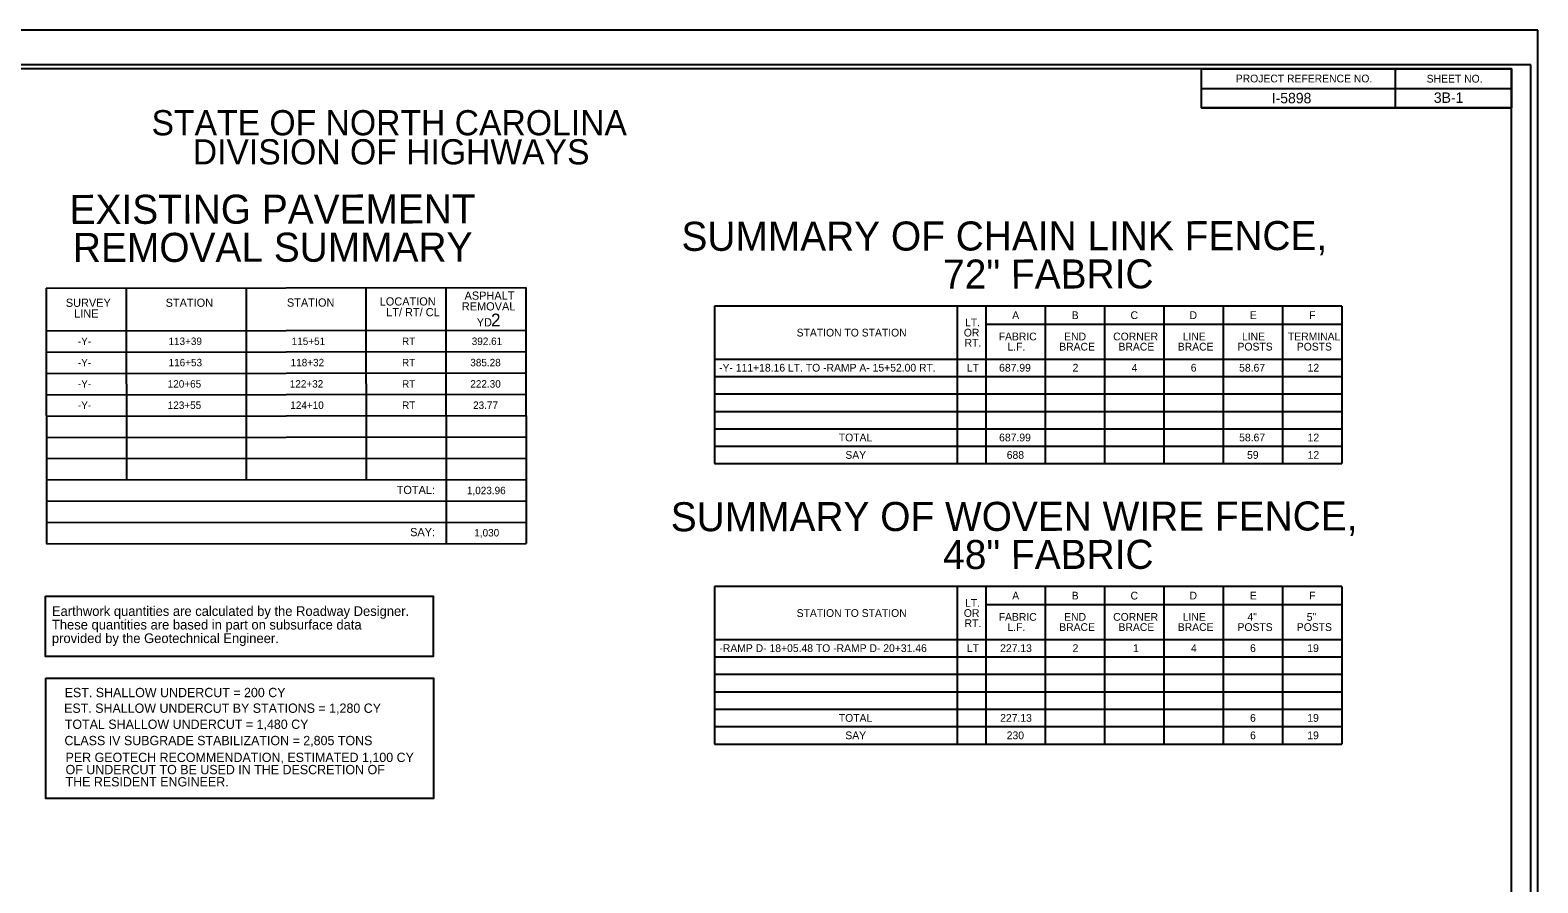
# Model space of a CAD drawing. Extents: x 573692 to 575376, y -53322 to -52222.
# Drawn here: x 574403 to 575376, y -52772 to -52222 of the extents above; entities that cross this region are included whole.
import ezdxf

# ---------------------------------------------------------------- set-up
doc = ezdxf.new("R2010")
doc.units = 0
for name, color, linetype in [('Prop Dimension Text', 7, 'Continuous'), ('Sheet Data Field CELL', 7, 'Continuous'), ('Sheet Plot Border Inside CELL', 7, 'Continuous'), ('Sheet Plot Border Outside CELL', 7, 'Continuous'), ('Sheet Summary Combination CELL', 7, 'Continuous'), ('Sheet Summary Combination Grid CELL', 7, 'Continuous'), ('Sheet Summary Earthwork CELL', 7, 'Continuous')]:
    doc.layers.add(name, color=color, linetype=linetype)

msp = doc.modelspace()

# ---------------------------------------------------------------- linework, layer by layer
at = {"layer": 'Sheet Plot Border Inside CELL'}
msp.add_lwpolyline([(575371.32, -52244.93), (573704.82, -52244.93), (573704.82, -53300.03), (575371.32, -53300.03)], close=True, dxfattribs=at)
at = {"layer": 'Sheet Plot Border Outside CELL'}
msp.add_lwpolyline([(575375.82, -52222.48), (573691.82, -52222.48), (573691.82, -53322.48), (575375.82, -53322.48)], close=True, dxfattribs=at)
at = {"layer": 'Sheet Summary Combination CELL'}
for p, q in [((575283.82, -52247.53), (575283.82, -52272.53)), ((575158.77, -52260.03), (575358.82, -52260.03)), ((575158.77, -52272.53), (575358.82, -52272.53)), ((574568.98, -52388.77), (574568.98, -52388.77)), ((574575.86, -52388.87), (574575.86, -52388.87)), ((574585.81, -52388.64), (574585.81, -52388.64)), ((574591.97, -52388.75), (574591.97, -52388.75))]:
    msp.add_line(p, q, dxfattribs=at)
for points in [[(575358.82, -52247.48), (573858.82, -52247.48), (573858.82, -53297.48), (575358.82, -53297.48)], [(575158.77, -52247.48), (575358.82, -52247.48), (575358.82, -52272.53), (575158.77, -52272.53)]]:
    msp.add_lwpolyline(points, close=True, dxfattribs=at)
at = {"layer": 'Sheet Summary Combination Grid CELL'}
for p, q in [((574413.61, -52388.88), (574723.09, -52388.56)), ((574413.61, -52388.88), (574413.78, -52553.88)), ((574465.2, -52388.82), (574465.33, -52512.57)), ((574542.58, -52388.74), (574542.71, -52512.49)), ((574619.91, -52388.66), (574620.04, -52512.41)), ((574671.5, -52388.61), (574671.67, -52553.61)), ((574723.09, -52388.56), (574723.26, -52553.56)), ((574723.09, -52388.56), (574723.26, -52553.56)), ((574844.82, -52400.56), (574844.82, -52502.1)), ((575249.3, -52400.56), (574844.82, -52400.56)), ((575001.3, -52400.56), (575001.3, -52502.1)), ((575019.8, -52400.56), (575019.8, -52502.1)), ((575058.05, -52400.56), (575058.05, -52502.1)), ((575096.3, -52400.56), (575096.3, -52502.1)), ((575134.55, -52400.56), (575134.55, -52502.1)), ((575172.8, -52400.56), (575172.8, -52502.1)), ((575211.05, -52400.56), (575211.05, -52502.1)), ((575249.3, -52400.56), (575249.3, -52502.1)), ((574413.64, -52416.38), (574723.12, -52416.06)), ((575019.8, -52412.1), (575249.3, -52412.1)), ((574413.65, -52430.13), (574723.14, -52429.81)), ((574844.82, -52434.6), (575249.3, -52434.6)), ((574413.67, -52443.88), (574723.15, -52443.56)), ((574844.82, -52445.85), (575249.3, -52445.85)), ((574413.68, -52457.63), (574723.16, -52457.31)), ((574844.82, -52457.1), (575249.3, -52457.1)), ((574844.82, -52468.35), (575249.3, -52468.35)), ((574413.69, -52471.38), (574723.18, -52471.06)), ((574413.71, -52485.13), (574723.19, -52484.81)), ((574844.82, -52479.6), (575249.3, -52479.6)), ((574844.82, -52490.85), (575249.3, -52490.85)), ((574413.72, -52498.88), (574723.21, -52498.56)), ((574844.82, -52502.1), (575249.3, -52502.1)), ((574413.74, -52512.63), (574723.22, -52512.31)), ((574413.75, -52526.38), (574723.24, -52526.06)), ((574413.77, -52540.13), (574723.25, -52539.81)), ((574413.78, -52553.88), (574723.26, -52553.56)), ((574844.82, -52581.44), (574844.82, -52682.98)), ((575249.3, -52581.44), (574844.82, -52581.44)), ((575001.3, -52581.44), (575001.3, -52682.98)), ((575019.8, -52581.44), (575019.8, -52682.98)), ((575058.05, -52581.44), (575058.05, -52682.98)), ((575096.3, -52581.44), (575096.3, -52682.98)), ((575134.55, -52581.44), (575134.55, -52682.98)), ((575172.8, -52581.44), (575172.8, -52682.98)), ((575211.05, -52581.44), (575211.05, -52682.98)), ((575249.3, -52581.44), (575249.3, -52682.98)), ((575019.8, -52592.98), (575249.3, -52592.98)), ((574844.82, -52615.48), (575249.3, -52615.48)), ((574844.82, -52626.73), (575249.3, -52626.73)), ((574844.82, -52637.98), (575249.3, -52637.98)), ((574844.82, -52649.23), (575249.3, -52649.23)), ((574844.82, -52660.48), (575249.3, -52660.48)), ((574844.82, -52671.73), (575249.3, -52671.73)), ((574844.82, -52682.98), (575249.3, -52682.98))]:
    msp.add_line(p, q, dxfattribs=at)
at = {"layer": 'Sheet Summary Earthwork CELL'}
for points in [[(574413.11, -52587.5), (574663.17, -52587.5), (574663.17, -52626.53), (574413.11, -52626.53)], [(574413.32, -52640.49), (574663.37, -52640.49), (574663.37, -52718.03), (574413.32, -52718.03)]]:
    msp.add_lwpolyline(points, close=True, dxfattribs=at)

# ---------------------------------------------------------------- texts
at = {"layer": 'Prop Dimension Text'}
for s, height, p in [('LT.', 5, (575006.35, -52413.52)), ('A', 5, (575036.76, -52408.83)), ('B', 5, (575075.14, -52408.83)), ('C', 5, (575113.09, -52408.83)), ('D', 5, (575151.15, -52408.83)), ('E', 5, (575190.08, -52408.83)), ('F', 5, (575228.33, -52408.83)), ('STATION TO STATION', 5.0001, (574897.72, -52420.08)), ('OR', 5, (575005.57, -52420.08)), ('FABRIC', 5, (575028.05, -52422.57)), ('END', 5, (575070.28, -52422.57)), ('CORNER', 5, (575101.89, -52422.57)), ('LINE', 5, (575146.73, -52422.57)), ('LINE', 5, (575184.98, -52422.57)), ('TERMINAL', 5, (575214.61, -52422.57)), ('RT.', 5, (575006.06, -52426.63)), ('L.F.', 5, (575033.69, -52429.12)), ('BRACE', 5, (575067.09, -52429.12)), ('BRACE', 5, (575105.34, -52429.12)), ('BRACE', 5, (575143.59, -52429.12)), ('POSTS', 5, (575182.1, -52429.12)), ('POSTS', 5, (575220.35, -52429.12)), ('-Y- 111+18.16 LT. TO -RAMP A- 15+52.00 RT.', 5.0001, (574847.69, -52442.72)), ('LT', 5, (575007.58, -52442.72)), ('687.99', 5, (575028.33, -52442.72)), ('2', 5, (575075.71, -52442.72)), ('4', 5, (575113.82, -52442.72)), ('6', 5, (575151.95, -52442.72)), ('58.67', 5, (575183.15, -52442.72)), ('12', 5, (575227.33, -52442.72)), ('TOTAL', 5, (574924.93, -52487.72)), ('687.99', 5, (575028.33, -52487.72)), ('58.67', 5, (575183.15, -52487.72)), ('12', 5, (575227.33, -52487.72)), ('SAY', 5, (574929.13, -52498.97)), ('688', 5, (575033.23, -52498.97)), ('59', 5, (575188.25, -52498.97)), ('12', 5, (575227.33, -52498.97)), ('A', 5, (575036.76, -52589.71)), ('B', 5, (575075.14, -52589.71)), ('C', 5, (575113.09, -52589.71)), ('D', 5, (575151.15, -52589.71)), ('E', 5, (575190.08, -52589.71)), ('F', 5, (575228.33, -52589.71)), ('LT.', 5, (575006.35, -52594.4)), ('STATION TO STATION', 5.0001, (574897.72, -52600.96)), ('OR', 5, (575005.57, -52600.96)), ('RT.', 5, (575006.06, -52607.51)), ('FABRIC', 5, (575028.05, -52603.45)), ('END', 5, (575070.28, -52603.45)), ('CORNER', 5, (575101.89, -52603.45)), ('LINE', 5, (575146.73, -52603.45)), ('4"', 5, (575188.5, -52603.45)), ('5"', 5, (575226.75, -52603.45)), ('L.F.', 5, (575033.69, -52610.01)), ('BRACE', 5, (575067.09, -52610.01)), ('BRACE', 5, (575105.34, -52610.01)), ('BRACE', 5, (575143.59, -52610.01)), ('POSTS', 5, (575182.1, -52610.01)), ('POSTS', 5, (575220.35, -52610.01)), ('-RAMP D- 18+05.48 TO -RAMP D- 20+31.46', 5.0001, (574847.89, -52623.6)), ('LT', 5, (575007.58, -52623.6)), ('227.13', 5, (575028.99, -52623.6)), ('2', 5, (575075.71, -52623.6)), ('1', 5, (575114.67, -52623.6)), ('4', 5, (575152.07, -52623.6)), ('6', 5, (575190.2, -52623.6)), ('19', 5, (575227.1, -52623.6)), ('TOTAL', 5, (574924.93, -52668.6)), ('227.13', 5, (575028.99, -52668.6)), ('6', 5, (575190.2, -52668.6)), ('19', 5, (575227.1, -52668.6)), ('SAY', 5, (574929.13, -52679.85)), ('230', 5, (575033.23, -52679.85)), ('6', 5, (575190.2, -52679.85)), ('19', 5, (575227.1, -52679.85))]:
    msp.add_text(s, height=height, dxfattribs=at).set_placement(p)
at = {"layer": 'Sheet Data Field CELL'}
for s, p in [('I-5898', (575204.14, -52269.68)), ('3B-1', (575308.75, -52269.38))]:
    msp.add_text(s, height=6.75, dxfattribs=at).set_placement(p)
at = {"layer": 'Sheet Summary Combination CELL'}
for s, height, p in [('PROJECT REFERENCE NO.', 5.0001, (575180.97, -52256.18)), ('SHEET NO.', 5, (575304.12, -52256.28)), ('STATE OF NORTH CAROLINA', 16.2501, (574481.57, -52290.32)), ('DIVISION OF HIGHWAYS', 16.2501, (574508.17, -52309.07)), ('-Y- ', 4.8, (574434.07, -52425.55)), ('113+39', 4.8, (574492.5, -52425.55)), ('115+51', 4.8, (574571.99, -52425.55)), ('RT', 4.8, (574643.16, -52425.55)), ('392.61', 4.8, (574688.13, -52425.55)), ('-Y- ', 4.8, (574434.08, -52439.3)), ('116+53', 4.8, (574492.58, -52439.3)), ('118+32', 4.8, (574571.32, -52439.3)), ('RT', 4.8, (574643.17, -52439.3)), ('385.28', 4.8, (574687.2, -52439.3)), ('-Y- ', 4.8, (574434.1, -52453.05)), ('120+65', 4.8, (574492.01, -52453.05)), ('122+32', 4.8, (574570.76, -52453.05)), ('RT', 4.8, (574643.19, -52453.05)), ('222.30', 4.8, (574687.21, -52453.05)), ('-Y- ', 4.8, (574434.11, -52466.8)), ('123+55', 4.8, (574492.03, -52466.8)), ('124+10', 4.8, (574571.09, -52466.8)), ('RT', 4.8, (574643.2, -52466.8)), ('23.77', 4.8, (574689.01, -52466.8)), ('1,023.96', 4.8, (574685.03, -52521.8)), ('1,030', 4.8, (574689.78, -52549.07)), ('EST. SHALLOW UNDERCUT = 200 CY', 6, (574425.55, -52652.72)), ('EST. SHALLOW UNDERCUT BY STATIONS = 1,280 CY', 6, (574425.19, -52662.82)), ('TOTAL SHALLOW UNDERCUT = 1,480 CY', 6, (574425.63, -52673.18)), ('CLASS IV SUBGRADE STABILIZATION = 2,805 TONS', 6, (574425.42, -52683.69)), ('PER GEOTECH RECOMMENDATION, ESTIMATED 1,100 CY', 6, (574426.12, -52694.55)), ('OF UNDERCUT TO BE USED IN THE DESCRETION OF', 6, (574426.12, -52702.42)), ('THE RESIDENT ENGINEER.', 6, (574426.12, -52710.28))]:
    msp.add_text(s, height=height, dxfattribs=at).set_placement(p)
for s, height, rotation, p in [('EXISTING PAVEMENT ', 18.75, 0.07143, (574428.76, -52347.47)), ('SUMMARY OF CHAIN LINK FENCE,', 18.75, 0.07143, (574823.42, -52364.85)), ('REMOVAL SUMMARY', 18.75, 0.07143, (574430.89, -52372.05)), ('72" FABRIC', 18.75, 0.07143, (574992.22, -52389.23)), ('SURVEY', 5.28, 0.0595, (574426.29, -52400.95)), ('STATION', 5.28, 0.0595, (574490.68, -52400.94)), ('STATION', 5.28, 0.0595, (574568.93, -52400.84)), ('LOCATION', 5.28, 0.0595, (574628.78, -52400.1)), ('REMOVAL', 5.28, 0.0595, (574681.74, -52403.29)), ('ASPHALT ', 5.28, 0.0595, (574683.5, -52396.36)), ('LINE', 5.28, 0.0595, (574431.7, -52407.88)), ('LT/ RT/ CL', 5.28, 0.0595, (574632.95, -52407.03)), ('TOTAL:', 5.28, 0.0595, (574639.71, -52521.72)), ('SUMMARY OF WOVEN WIRE FENCE,', 18.75, 0.07143, (574816.52, -52545.74)), ('SAY:', 5.28, 0.0595, (574648.37, -52548.89)), ('48" FABRIC', 18.75, 0.07143, (574992.22, -52570.11))]:
    msp.add_text(s, height=height, rotation=rotation, dxfattribs=at).set_placement(p)
at = {"layer": 'Sheet Summary Combination Grid CELL'}
for s, height, p in [('YD', 5.28, (574691.36, -52413.57)), ('2', 8.25, (574700.57, -52413.56))]:
    msp.add_text(s, height=height, rotation=0.0595, dxfattribs=at).set_placement(p)
at = {"layer": 'Sheet Summary Earthwork CELL'}
for s, p in [('Earthwork quantities are calculated by the Roadway Designer.', (574417.32, -52600.32)), ('These quantities are based in part on subsurface data ', (574417.32, -52609.07)), ('provided by the Geotechnical Engineer.', (574417.32, -52617.82))]:
    msp.add_text(s, height=6.25, dxfattribs=at).set_placement(p)

doc.saveas('drawing.dxf')
